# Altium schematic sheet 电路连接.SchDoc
size A4
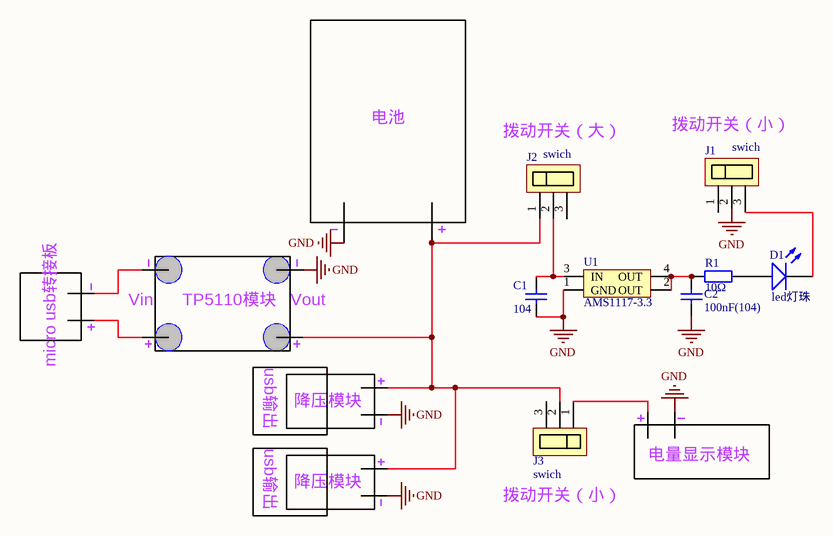
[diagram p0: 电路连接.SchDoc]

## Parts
C1  104  [LC-0805_C]
C2  100nF(104)  [LC-0805_C]
D1  led灯珠  [LC-0805_LED_S1]
J1  swich  [拨动开关]
J2  swich  [拨动开关]
J3  swich  [拨动开关]
R1  10Ω  [LC-0805_R]
U1  AMS1117-3.3  [AMS1117]

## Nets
GND: C1.1 C2.1 U1.1(GND)
NetC1_2: C1.2 J2.2 U1.3(IN)
NetC2_2: C2.2 R1.2 U1.2(OUT) U1.4(OUT)
NetD1_A: D1.A R1.1
NetD1_K: D1.K J1.3
NetJ2_1: J2.1 J3.2

Not connected (* = marked no-connect by the designer): J1 1 2; J2 3; J3 1 3

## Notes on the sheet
- 电池
- (near J2) 拨动开关（大）
- (near J1) 拨动开关（小）
- Vin
- TP5110模块
- Vout
- micro usb转接板
- usb输出
- 降压模块
- 拨动开关（小）
- 电量显示模块
- Labels drawn without touching a wire or pin: GND

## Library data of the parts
C1 C2 = 0805 100nF(104) 10% 50V: 贴片电容
D1 = 0805 白灯: 发光二极管
J1-J3 = 拨动开关
R1 = 0805 10Ω (10R0) 1%: 贴片电阻
U1 = AMS1117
